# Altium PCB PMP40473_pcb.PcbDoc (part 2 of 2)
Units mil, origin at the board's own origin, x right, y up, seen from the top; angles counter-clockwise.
Board outline 3937.01 x 2598.43 mil, 2 copper layers (Top Layer, Bottom Layer), stack 62 mil thick; 79 components, 45 nets, 178 pads, 0 vias.
Unrouted connection lines stored in the file: 2.
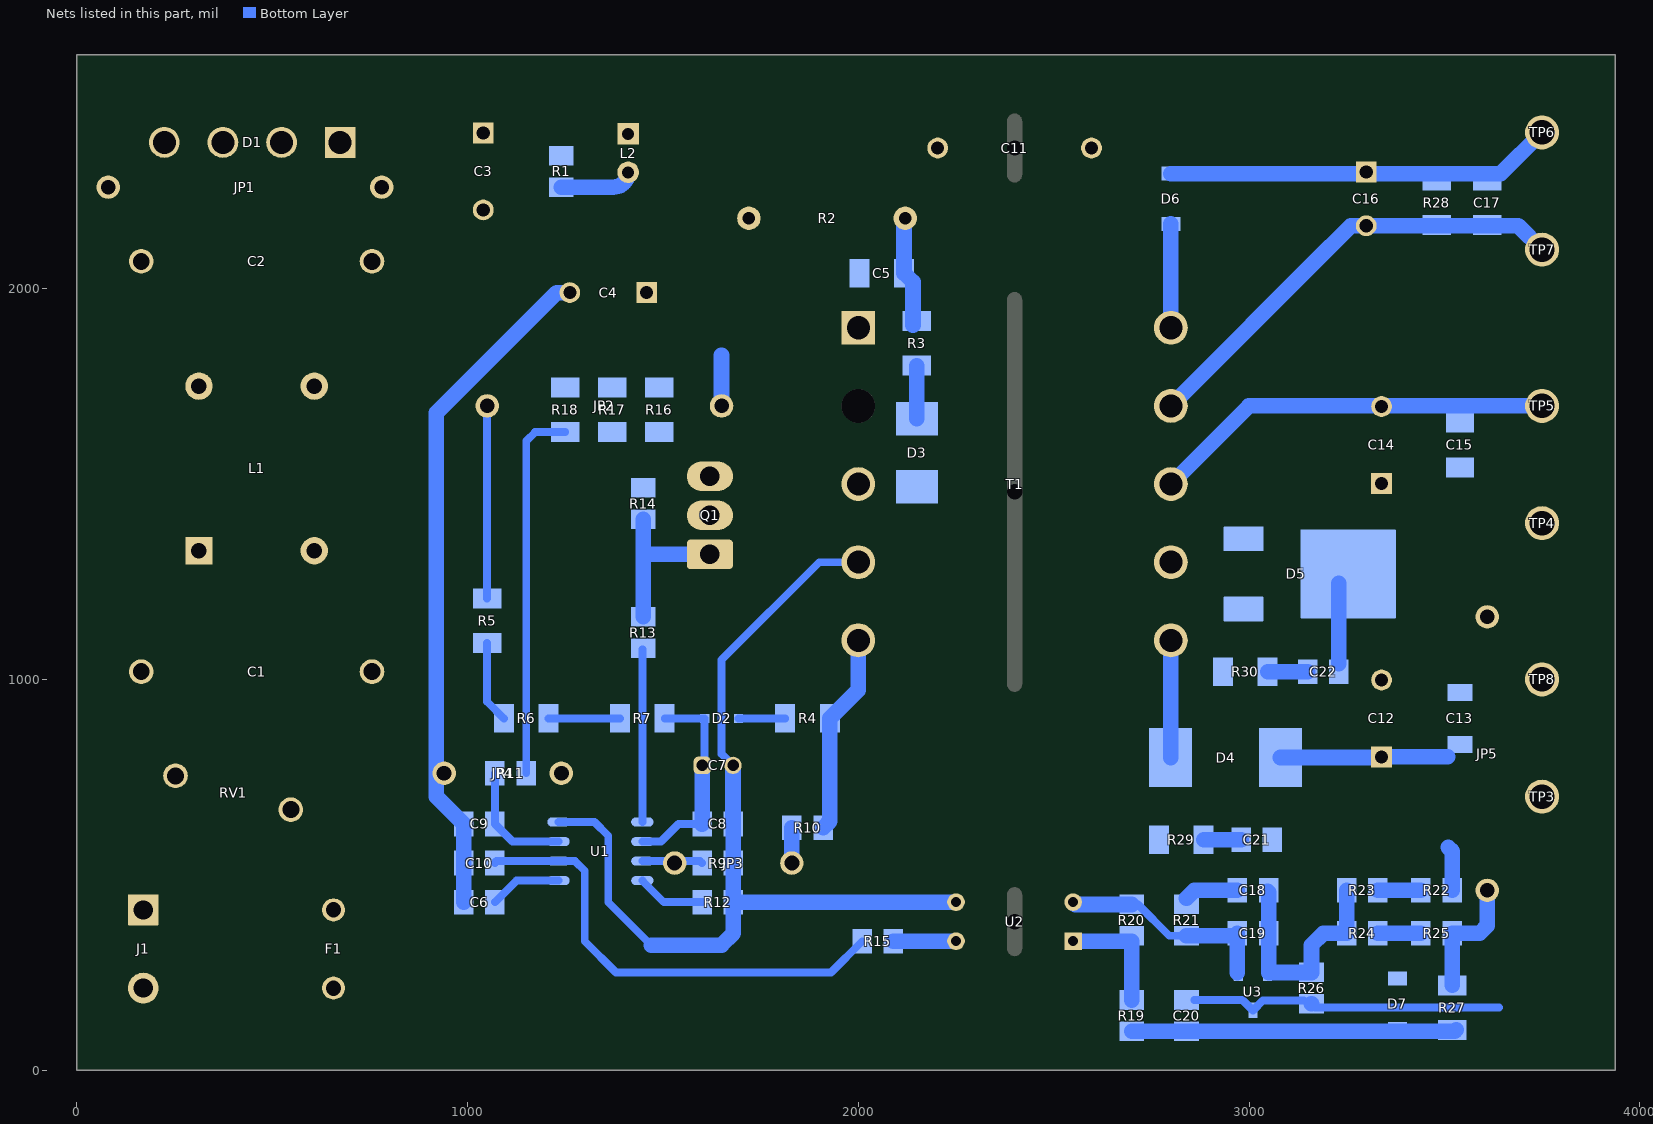
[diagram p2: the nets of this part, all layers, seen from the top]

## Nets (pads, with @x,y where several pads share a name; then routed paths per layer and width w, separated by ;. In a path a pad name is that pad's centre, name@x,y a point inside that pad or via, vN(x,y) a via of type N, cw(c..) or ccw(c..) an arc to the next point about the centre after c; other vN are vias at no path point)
12V: C14.1 C15.1 C22.2 D5.4 JP5.2 TP4.1 | length 206.1
  Bottom Layer w40: C22.2@3230,1040 D5.4@3230,1246.14
15V: C16.1 C17.1 D6.1 R28.2 TP6.1 | length 993.7
  Bottom Layer w40: D6.1@2800,2294.47 3644.47,2294.47 TP6.1@3750,2400
24V: C12.1 C13.1 C21.2 D4.1 R22.2 TP3.1 | length 542.8
  Bottom Layer w40: D4.1@3080.49,800 3337.8,800 C12.1@3339.37,801.57 3508.5,801.57 ; 3510,570 3520,560 R22.2@3520,460
NetC1_1: C1.1 F1.2 L1.2 RV1.2
NetC1_2: C1.2 J1.1 L1.1 RV1.1
NetC2_1: C2.1 D1.2 L1.3
NetC2_2: C2.2 D1.3 L1.4
NetC3_1: C3.1 D1.1 L2.1 R1.1
NetC4_1: C4.1 C5.1 JP2.2 L2.2 R1.2 R2.2 T1.1 | length 322.6
  Bottom Layer w40: R1.2@1240,2260 1373.07,2260 ccw(c1373.07,2297.87) L2.2@1410.95,2297.87 ; JP2.2@1650,1700 1650,1830
NetC5_2: C5.2 R2.1 R3.2 | length 283.6
  Bottom Layer w40: R2.1@2120,2180 2117.09,2177.09 C5.2@2117.09,2040 2140,2017.09 R3.2@2140,1907.09
NetC6_2: C6.2 U1.1 | length 185.5
  Bottom Layer w20: C6.2@1070,430 1125,485 U1.1@1232.72,485
NetC7_1: C7.1 C8.1 D2.1 R7.1 U1.6 | length 546.5
  Bottom Layer w20: U1.6@1447.28,585 1495,585 1540,630 C8.1@1600,630 ; R7.1@1504.37,900 D2.1@1606.69,900 1606.69,786.06 C7.1@1600.63,780
  Bottom Layer w40: C8.1@1600,630 1600.63,630.63 C7.1@1600.63,780
NetC9_1: C9.1 R11.1 U1.3 | length 311.4
  Bottom Layer w20: R11.1@1070,760 C9.1@1070,630 1115,585 U1.3@1232.72,585
NetC10_1: C10.1 R15.2 U1.2 | length 1199.5
  Bottom Layer w20: C10.1@1070,530 cw(c1075,530) 1075,535 U1.2@1232.72,535 1275,535 1300,510 1300,330 1380,250 1930,250 R15.2@2010,330
NetC16_2: C16.2 C17.2 R28.1 T1.9 TP7.1 | length 1745.7
  Bottom Layer w40: 3208.9,2110 2800,1701.1 T1.9@2800,1700 3261.1,2161.1 C16.2@3300,2161.1 3688.9,2161.1 TP7.1@3750,2100
NetC18_1: C18.1 C19.1 R23.1 R24.1 R26.2 U3.2 | length 897.8
  Bottom Layer w20: C18.1@3047.4,457.4 U3.2@3047.4,247.24 R26.2@3134.25,247.24
  Bottom Layer w40: C18.1@3047.4,457.4 3050.16,454.65 3050.16,250 R26.2@3160,250 3160,320 3190,350 R24.1@3250,350 R23.1@3250,460
NetC18_2: C18.2 R21.1 | length 138.3
  Bottom Layer w40: R21.1@2840,440 2860,460 C18.2@2970,460
NetC19_2: C19.2 R20.2 R21.2 U2.2 U3.1 | length 560.9
  Bottom Layer w20: R20.2@2700,424 2716,424 2796,344 R21.2@2840,344 ; U3.1@2972.6,247.24 U3.1@2972.6,249.84
  Bottom Layer w40: U2.2@2550,430 2556,424 R20.2@2700,424 ; R21.2@2840,344 2964,344 C19.2@2970,350 U3.1@2970,249.84
NetC20_1: C20.1 D7.1 R19.1 R27.2 | length 831.4
  Bottom Layer w40: R19.1@2700,99.5 C20.1@2840,99.5 3526.59,99.5 R27.2@3530,102.91
NetC21_1: C21.1 R29.1 | length 96.3
  Bottom Layer w40: R29.1@2883.73,590 C21.1@2980,590
NetC22_1: C22.1 R30.1 | length 102.4
  Bottom Layer w40: R30.1@3047.64,1020 C22.1@3150,1020
NetD2_2: D2.2 R4.1 | length 119.6
  Bottom Layer w20: D2.2@1693.31,900 R4.1@1812.91,900
NetD3_1: D3.1 R3.1 | length 135.9
  Bottom Layer w40: D3.1@2150,1667.01 R3.1@2150,1802.91
NetD3_2: D3.2 Q1.2 T1.3
NetD4_2: D4.2 R29.2 T1.6 | length 300.2
  Bottom Layer w40: D4.2@2799.51,800 2800,800.49 T1.6@2800,1100
NetD5_1: D5.1 D5.3 R30.2 T1.7
NetD6_2: D6.2 T1.10 | length 265.5
  Bottom Layer w40: T1.10@2800,1900 D6.2@2800,2165.53
NetF1_1: F1.1 J1.2
NetJP2_1: JP2.1 R5.2 | length 492.9
  Bottom Layer w20: R5.2@1050,1207.09 JP2.1@1050,1700
NetJP3_1: JP3.1 R9.2 U1.7 | length 154.8
  Bottom Layer w20: U1.7@1447.28,535 1595,535 R9.2@1600,530
NetJP3_2: JP3.2 R10.1 | length 90
  Bottom Layer w40: JP3.2@1830,530 R10.1@1830,620
NetJP5_1: JP5.1 R25.2 R27.1 | length 321.2
  Bottom Layer w40: R27.1@3520,217.09 R25.2@3520,350 3590,350 3610,370 JP5.1@3610,460
NetQ1_1: Q1.1 R13.1 R14.2 | length 420
  Bottom Layer w40: R13.1@1450,1160 1450,1320 ; R14.2@1450,1410 1450,1320 ; Q1.1@1620,1320 1450,1320
NetQ1_3: Q1.3 R11.2 R14.1 R16.2 R17.2 R18.2 | length 959.5
  Bottom Layer w20: R11.2@1150,760 1150,1610 1172.91,1632.91 R18.2@1250,1632.91
NetR4_2: R4.2 R10.2 T1.5 | length 517.3
  Bottom Layer w40: R10.2@1910,620 1927.09,637.09 R4.2@1927.09,900 2000,972.91 T1.5@2000,1100
NetR5_1: R5.1 R6.2 | length 210.7
  Bottom Layer w20: R5.1@1050,1092.91 1050,942.91 R6.2@1092.91,900
NetR6_1: R6.1 R7.2 | length 183.1
  Bottom Layer w20: R6.1@1207.09,900 R7.2@1390.2,900
NetR12_2: R12.2 U1.8 | length 175.5
  Bottom Layer w20: U1.8@1447.28,485 1502.28,430 R12.2@1600,430
NetR13_2: R13.2 U1.5 | length 442.3
  Bottom Layer w20: U1.5@1447.28,635 R13.2@1447.28,1077.28
NetR15_1: R15.1 U2.4 | length 160
  Bottom Layer w40: R15.1@2090,330 U2.4@2250,330
NetR19_2: R19.2 R20.1 U2.1 | length 300.5
  Bottom Layer w40: U2.1@2550,330 2700,330 R19.2@2700,179.5
NetR22_1: R22.1 R23.2 | length 110
  Bottom Layer w40: R23.2@3330,460 R22.1@3440,460
NetR24_2: R24.2 R25.1 | length 110
  Bottom Layer w40: R24.2@3330,350 R25.1@3440,350
PGND: C3.2 C4.2 C6.1 C7.2 C8.2 C9.2 C10.2 C11.1 D1.4 JP1.1 JP1.2 JP4.1 JP4.2 R9.1 R12.1 R16.1 R17.1 R18.1 T1.4 U1.4 U2.3 | length 4175.9
  Bottom Layer w20: U1.4@1232.72,635 1325,635 1360,600 1360,430 1470,320 ; C7.2@1679.37,780 1650,809.37 1650,1050 1900,1300 T1.4@2000,1300
  Bottom Layer w40: C6.1@990,430 C10.2@990,530 C9.2@990,630 920,700 920,1682 1228,1990 C4.2@1261.57,1990 ; 1470,320 1650,320 1680,350 R12.1@1680,430 ; C7.2@1679.37,780 1679.37,630.63 C8.2@1680,630 R12.1@1680,430 ; U2.3@2250,430 R12.1@1680,430
SGND: C11.2 C12.2 C13.2 C14.2 C15.2 C20.2 D7.2 R26.1 T1.8 TP5.1 TP8.1 U3.3 | length 1818.7
  Bottom Layer w20: C20.2@2860,179.5 2983.26,179.5 U3.3@3010,152.76 3035.75,178.5 R26.1@3140,178.5 ; R26.1@3160,170 3170,160 3640,160
  Bottom Layer w40: T1.8@2800,1500 3000,1700 TP5.1@3750,1700
pads on no net: T1.2

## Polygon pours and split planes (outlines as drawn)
NetC20_1 on Bottom Layer "Aux" (solid, pour order 56): 3550,25.49 cw(c3534.51,25.49) 3534.51,10 2675.49,10 cw(c2675.49,25.49) 2660,25.49 2660,109.02 cw(c2670,109.02) 2670,119.02 3550,119.02
NetR4_2 on Bottom Layer "Aux" (solid, pour order 50): 2060,1170 cw(c2060,1160) 2070,1160 2070,570 1885,570 1885,1160 cw(c1895,1160) 1895,1170 1905,1170
NetC7_1 on Bottom Layer "VCC" (solid, pour order 54): 1518.56,586.5 1492.26,570.02 1492.22,570.01 1492.18,570 1410,570 1410,600 1440,610 1500,610 1500,920 1516.81,936.81 1613.19,936.81 1620,930 1620,600 1606.5,586.5
PGND on Bottom Layer "PGND" (solid, remove dead copper, pour order 52): 2230,1340 2220,1350 2180,1350 1560,1350 1560,835 1520,810 1030,810 1030,380 970,440 970,990 940,1020 900,1020 900,0 2200,0 2230,0
NetQ1_3 on Bottom Layer "Bottom Layer-No Net" (solid, remove dead copper, pour order 40): 1220,1480 cw(c1220,1500) 1200,1500 1200,1650 cw(c1220,1650) 1220,1670 1580,1670 1690,1560 1690,1491.15 1678.85,1480
NetC2_1 on Bottom Layer "Bottom Layer-No Net" (solid, remove dead copper, pour order 38): 470,2450 cw(c480,2450) 480,2460 560,2460 cw(c560,2450) 570,2450 570,2420 570,2290 640,2220 700,2160 790,2160 cw(c790,2150) 800,2150 800,1716.02 cw(c783.98,1716.02) 783.98,1700 780,1700 490,1700 cw(c490,1720) 470,1720 470,2040 cw(c490,2040) 490,2060 710,2060 ccw(c710,2070) 720,2070 ccw(c710,2070) 710,2080 488.24,2080 cw(c488.24,2098.05) 470.19,2098.05 cw(c480,2100) 470,2100 470,2410
NetC2_2 on Bottom Layer "Bottom Layer-No Net" (solid, remove dead copper, pour order 36): 320,2450 cw(c330,2450) 330,2460 410,2460 cw(c410,2450) 420,2450 420,2420 420,2090 cw(c410,2090) 410,2080 210,2080 ccw(c210,2070) 200,2070 ccw(c210,2070) 210,2060 360,2060 cw(c360,2050) 370,2050 370,1720 cw(c350,1720) 350,1700 40,1700 cw(c40,1714.51) 25.49,1714.51 25.49,2050 cw(c35.49,2050) 35.49,2060 120,2060 ccw(c120,2070) 130,2070 ccw(c120,2070) 120,2080 33.5,2080 cw(c33.5,2088.01) 25.49,2088.01 25.49,2175.49 cw(c38.98,2175.49) 38.98,2188.98 191.02,2188.98 320,2317.95
NetC1_1 on Bottom Layer "Bottom Layer-No Net" (solid, remove dead copper, pour order 34): 490,360 cw(c490,380) 470,380 470,400 470,1000 470,1010 710,1010 ccw(c710,1020) 720,1020 ccw(c710,1020) 710,1030 470,1030 470,1380 cw(c490,1380) 490,1400 780,1400 cw(c780,1380) 800,1380 800,410 800,380 cw(c780,380) 780,360 750,360 560,360
NetC1_2 on Bottom Layer "Bottom Layer-No Net" (solid, remove dead copper, pour order 32): 370,400 370,380 cw(c350,380) 350,360 330,360 40,360 cw(c40,374.51) 25.49,374.51 25.49,1000 cw(c35.49,1000) 35.49,1010 120,1010 ccw(c120,1020) 130,1020 ccw(c120,1020) 120,1030 40,1030 cw(c40,1044.51) 25.49,1044.51 25.49,1385.49 cw(c40,1385.49) 40,1400 50,1400 350,1400 cw(c350,1380) 370,1380 370,1039.62 370,1030 210,1030 ccw(c210,1020) 200,1020 ccw(c210,1020) 210,1010 370,1010 370,1000
NetF1_1 on Bottom Layer "Bottom Layer-No Net" (solid, remove dead copper, pour order 30): 25.49,44.51 25.49,245.49 cw(c40,245.49) 40,260 780,260 785.49,260 cw(c785.49,245.49) 800,245.49 800,44.51 cw(c785.49,44.51) 785.49,30 780,30 40,30 cw(c40,44.51)
NetD6_2 on Bottom Layer "Bottom Layer-No Net" (solid, remove dead copper, pour order 16): 2650,1830 ccw(c2664.51,1830) 2664.51,1815.49 2785.49,1815.49 2990,2020 2990,2200 ccw(c2980,2200) 2980,2210 2660,2210 ccw(c2660,2200) 2650,2200 2650,2190
SGND on Bottom Layer "Bottom Layer-No Net" (solid, remove dead copper, pour order 14): 2660,1604.51 ccw(c2660,1594.51) 2650,1594.51 2650,1590 2650,540 2650,80 2660,70 3920,70 3920,1970 3911.52,1970 3911.52,2596.91 3908.43,2600 2770,2600 2708.43,2598.43 2560,2450 2560,2300 2570,2290 2700,2290 2720,2270 2720,1604.51
NetD5_1 on Bottom Layer "Bottom Layer-No Net" (solid, pour order 12): 2903.11,930 cw(c2903.11,937.05) 2896.06,937.05 2896.06,1127.24 2853.3,1170 2670,1170 2660,1170 cw(c2660,1180) 2650,1180 2650,1390 cw(c2660,1390) 2660,1400 2670,1400 3070,1400 3070,1070 2997.05,1070 2997.05,937.05 cw(c2990,937.05) 2990,930
24V on Bottom Layer "Bottom Layer-No Net" (solid, pour order 10): 3050,540 cw(c3050,560) 3030,560 3030,640 ccw(c3020,640) 3020,650 2901.42,650 cw(c2901.42,651.42) 2900,651.42 2900,870 cw(c2910,870) 2910,880 3810,880 cw(c3805,855) 3830,850 3830,560 cw(c3810,560) 3810,540
NetD4_2 on Bottom Layer "Bottom Layer-No Net" (solid, pour order 8): 2840,1140 cw(c2840,1120) 2860,1120 2860,566.86 2833.14,540 2650,540 2650,1130 cw(c2660,1130) 2660,1140 2670,1140
12V on Bottom Layer "Bottom Layer-No Net" (solid, pour order 6): 3120,1140 ccw(c3140,1140) 3140,1120 3800,1120 ccw(c3800,1140) 3820,1140 3820,1560 ccw(c3795,1565) 3800,1590 3150,1590 ccw(c3150,1560) 3120,1560
NetC16_2 on Bottom Layer "Bottom Layer-No Net" (solid, pour order 2): 3810,2030 ccw(c3810,2050) 3830,2050 3830,2190 ccw(c3810,2190) 3810,2210 3220,2210 2800,1790 2660,1790 ccw(c2660,1780) 2650,1780 2650,1640 ccw(c2660,1640) 2660,1630 2800,1630 3200,2030
15V on Bottom Layer "Bottom Layer-No Net" (solid, pour order 0): 3810,2240 ccw(c3810,2260) 3830,2260 3830,2430 ccw(c3810,2430) 3810,2450 2720,2450 ccw(c2720,2430) 2700,2430 2700,2260 ccw(c2720,2260) 2720,2240
PGND on Bottom Layer "Bottom Layer-No Net" (solid, pour order 18): 25.49,2230 ccw(c35.49,2230) 35.49,2220 40,2220 180,2220 270,2310 270,2460 330,2520 2010,2520 2120,2410 2120,2300 2130,2290 2230,2290 2240,2300 2240,2450 2091.57,2598.43 2030,2598.43 30,2598.43 ccw(c30,2593.91) 25.49,2593.91
NetC4_1 on Bottom Layer "Bottom Layer-No Net" (solid, remove dead copper, pour order 20): 1520,2330 ccw(c1520,2320) 1510,2320 1510,2030 cw(c1500,2030) 1500,2020 cw(c1500,2030) 1490,2030 1490,2320 ccw(c1480,2320) 1480,2330 1475.49,2330 1370,2330 1320,2280 1320,2060 1590,1790 2040,1790 2040,2210 1920,2330
NetC5_2 on Bottom Layer "Bottom Layer-No Net" (solid, pour order 22): 2220,2230 2230,2220 2230,1870 2210,1850 2100,1850 2090,1850 2080,1860 2080,2220 2090,2230
PGND on Bottom Layer "BOTTOM_LAYER_PGND_P024" (solid, remove dead copper, pour order 24): 1139,1874 1130,1870 1110,1870 1099.15,1880.85 1099.15,1913.85 1064,1949 932,2081 932,2090.79 1018.71,2177.5 ccw(c1016.64,2179.57) 1014.58,2181.64 927.93,2095 918,2095 813,2200 710,2200 670,2240 670,2290 cw(c680,2290) 680,2300 1010,2300 1070,2240 1530,1780 1540,1770 1540,1730 cw(c1517.68,1730) 1517.68,1707.68 1162.32,1707.68 cw(c1162.32,1727) 1143,1727 1143,1860 1244,1961 1244,1966 1240,1970 1235,1970
NetC3_1 on Bottom Layer "Bottom Layer-No Net" (solid, remove dead copper, pour order 26): 1490,2370 cw(c1475.49,2370) 1475.49,2355.49 1355.49,2355.49 1330,2330 620,2330 620,2420 620,2440 cw(c650,2440) 650,2470 1470,2470 cw(c1470,2450) 1490,2450 1490,2440
NetD3_2 on Bottom Layer "Bottom Layer-No Net" (solid, remove dead copper, pour order 28): 1730,1570 1730,1519.42 1672.1,1461.51 1626.7,1456.7 1620,1450 1620,1390 1630,1380 1660,1380 2210,1380 ccw(c2210,1400) 2230,1400 2230,1580 ccw(c2205,1575) 2200,1600 1760,1600

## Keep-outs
Keep-Out Layer:
  text ".Layer_Name" at 577,-858.49 h60

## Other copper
Top Layer:
  text ".Layer_Name" at 577,-858.49 h60
Bottom Layer:
  text ".Layer_Name" at 577,-858.49 h60

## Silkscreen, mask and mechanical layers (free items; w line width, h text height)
Top Overlay:
  region: 3660,230 3360,230 3360,130 3660,130
  text "15V/20mA" at 3911.52,2046.02 h100 r90
  text "12V/0.9A" at 3910,1370 h100 r90
  text "24V/0.5A" at 3910,670 h100 r90
  text "'.PRJ_Number'.PCB_Rev-" at 2775,145.77 h108.27
  text "INPUT: 85-115VAC" at 440,40 h100
  text ".Layer_Name" at 577,-858.49 h60
Bottom Overlay:
  lines w5: 2242.52,0 2242.52,2598.43 ; 2555.48,0 2555.48,2598.43
  text ".Layer_Name" at 577,-858.49 h60
Top Paste:
  text ".Layer_Name" at 577,-858.49 h60
Bottom Paste:
  text ".Layer_Name" at 577,-858.49 h60
Top Solder:
  text ".Layer_Name" at 577,-858.49 h60
  text ".Layer_Name" at 577,-858.49 h60
Bottom Solder:
  text ".Layer_Name" at 577,-858.49 h60
Drill Guide:
  text ".Layer_Name" at 577,-858.49 h60
M1 Board Outline:
  the board outline again, w10
  text ".Layer_Name" at 577,-858.49 h60
M2 Board Dimensions:
  rectangle: 0,-275 125,-150
  rectangle: 125,-400 500,-275
  lines w7: 0,-275 1000,-275 ; 125,-400 125,-150 ; 250,-400 250,-150 ; 500,-400 500,-150 ; 750,-400 750,-150 ; 0,-400 1000,-400 1000,-150 0,-150 0,-400
  text ".Layer_Name" at 577,-858.49 h60
M3 3D STEP Top:
  text ".Layer_Name" at 577,-858.49 h60
M4 3D STEP Bottom:
  text ".Layer_Name" at 577,-858.49 h60
M5 Assembly Top:
  lines w10: -292,-930.17 6308,-930.17 ; -292,-726.83 6310,-726.83 ; -292,-523.5 -292,-1133.5 3713,-1133.5 6310,-1133.5 6310,-523.5 -291.5,-523.5 -291.5,-1133.5 1284,-1133.5 ; 2173,-1133.5 2173,-523.5 ; 3440,-726.83 3440,-523.5 ; 4280,-726.83 4280,-523.5 ; 4902,-1140 4902,-937.17
  text "COMPONENTS MARKED 'DNP' SHOULD NOT BE POPULATED." at 1153.5,-318.5 h60
  text "ASSEMBLY VARIANT:" at 1153,-434 h60
  text ".VariantName" at 2189,-434 h60
  text "PCB VIEWED FROM TOP SIDE" at -228.5,-655.67 h60
  text "BOARD #:" at 2248,-655.67 h60
  text ".PRJ_Number" at 2793.5,-655.67 h60
  text "REV:" at 3638,-655.67 h60
  text ".PCB_Rev" at 3929.5,-655.67 h60
  text "SVN REV:" at 4476,-655.67 h60
  text ".VersionControl_RevNumber" at 4982,-655.67 h60
  text "TID #:" at 2248,-859 h60
  text ".TID" at 2793.5,-859 h60
  text "PLOT NAME =" at -228.5,-1064.34 h60
  text ".plot_File_Name" at 577,-1064.34 h60
  text "GENERATED    :" at 2250,-1064.34 h60
  text ".Print_Date" at 3119.5,-1064.34 h60
  text ".Print_Time" at 3848.5,-1064.34 h60
  text "TEXAS INSTRUMENTS" at 5113,-1064.34 h60
M6 Assembly Bottom:
  lines w10: -292.5,-727.33 6309.5,-727.33 ; -290.5,-930.67 6309.5,-930.67 ; 1115.5,-1140.5 1115.5,-937.67 ; 1737.5,-727.33 1737.5,-524 ; 2577.5,-727.33 2577.5,-524 ; 3844.5,-1134 3844.5,-524 ; 4733.5,-1134 6309,-1134 6309,-524 -292.5,-524 -292.5,-1134 2304.5,-1134 6309.5,-1134 6309.5,-524
  text "COMPONENTS MARKED 'DNP' SHOULD NOT BE POPULATED." at 6102,-318 h60
  text ".VariantName" at 5058,-434 h60
  text "ASSEMBLY VARIANT:" at 6097,-434 h60
  text ".VersionControl_RevNumber" at 1035.5,-656.17 h60
  text "SVN REV:" at 1541.5,-656.17 h60
  text ".PCB_Rev" at 2088,-656.17 h60
  text "REV:" at 2379.5,-656.17 h60
  text ".PRJ_Number" at 3224,-656.17 h60
  text "BOARD #:" at 3769.5,-656.17 h60
  text "PCB VIEWED FROM BOTTOM SIDE" at 6246,-656.17 h60
  text ".TID" at 3224,-859.5 h60
  text "TID #:" at 3769.5,-859.5 h60
  text "TEXAS INSTRUMENTS" at 904.5,-1064.84 h60
  text ".Print_Time" at 2169,-1064.84 h60
  text ".Print_Date" at 2898,-1064.84 h60
  text "GENERATED    :" at 3767.5,-1064.84 h60
  text ".plot_File_Name" at 5440.5,-1064.84 h60
  text "PLOT NAME =" at 6246,-1064.84 h60
M9 Title Sheet:
  drawing of 57 lines, arcs and shapes, not listed
  text "1" at 739.84,8036.5 h70
  text "2" at 3235.5,8036.5 h70
  text "3" at 5724.84,8036.5 h70
  text "4" at 8231.51,8036.5 h70
  text "5" at 10730.5,8036.5 h70
  text "6" at 13235.5,8036.5 h70
  text "A" at -416.5,6893.5 h70
  text "A" at 14383.5,6893.5 h70
  text "B" at -416.5,4513.5 h70
  text "B" at 14383.5,4513.5 h70
  text "C" at -416.5,2138.5 h70
  text "C" at 14383.5,2138.5 h70
  text "PROJECT TITLE:" at 11343.5,277.5 h45
  text ".PRJ_Title" at 11393.5,144.17 h70
  text "DESIGNED FOR:" at 11343.5,-23.5 h45
  text ".PRJ_Customer" at 11393.5,-163.5 h70
  text "D" at -416.5,-231.5 h70
  text "D" at 14383.5,-231.5 h70
  text "FILE NAME:" at 11343.5,-323.5 h45
  text ".PCB_File_Name_No_Path" at 11393.5,-443.5 h70
  text "Texas Instruments (TI) and/or its licensors do not warrant the accuracy or completeness of this specification" at 6374,-605.34 h45
  text "ENGINEER:" at 11343.5,-613.5 h45
  text "LAYOUT BY:" at 12848.5,-613.5 h45
  text "or any information contained therein. TI and/or its licensors do not warrant that this design will meet" at 6329.01,-718 h45
  text ".PRJ_Engineer" at 11393.5,-768.49 h70
  text ".PCB_Layout" at 12899,-768.49 h70
  text "the specifications, will be suitable for your application or fit for any particular purpose, or will operate in" at 6329.01,-830.67 h45
  text ".Layer_Name" at 577,-858.49 h60
  text "ALTIUM DESIGNER VERSION:" at 12848.5,-923.5 h45
  text "an implementation. TI and/or its licensors do not warrant that the design is production worthy. You should" at 6329.01,-943.33 h45
  text "completely validate and test your design implementation to confirm the system functionality for your application." at 6374,-1056 h45
  text ".print_Scale" at 11393.5,-1056.83 h70
  text ".Application_BuildNumber" at 12899,-1056.83 h70
  text "1" at 739.84,-1263.5 h70
  text "2" at 3235.5,-1263.5 h70
  text "3" at 5724.84,-1263.5 h70
  text "4" at 8231.51,-1263.5 h70
  text "5" at 10730.5,-1263.5 h70
  text "6" at 13235.5,-1263.5 h70
M10 Fab Notes:
  drawing of 189 lines, arcs and shapes, not listed
  text "DESIGN INFORMATION" at 12382.02,6356.17 h60
  text "MIN. TRACK WIDTH:" at 11737.46,6224.05 h60
  text "8" at 12833.7,6224.05 h60
  text "MIL" at 12988.46,6224.05 h60
  text "MIN. CLEARANCE:" at 11737.46,6099.92 h60
  text "0.2" at 12773.7,6099.93 h60
  text "mm" at 12988.46,6099.92 h60
  text "MIN. VIA PAD SIZE:" at 11737.46,5975.8 h60
  text "24" at 12803.71,5975.8 h60
  text "MIL" at 12988.46,5975.8 h60
  text "0.05mm (2MIL)" at 12432.46,5845.9 h60
  text "MINIMUM ANNULAR RING" at 11408.23,5837.67 h60
  text "EXTERNAL" at 13140.46,5837.67 h60
  text "PER" at 11608.23,5727.55 h60
  text "IPC-D-275 CLASS 2 LEVEL C" at 11828.23,5727.54 h60
  text "MIL, HOLES" at 13316.46,5627.07 h60
  text "+/-" at 12924,5618.48 h60
  text "+/-" at 13778,5618.48 h60
  text "REGISTRATION TOLERANCES:" at 11408.23,5617.42 h60
  text "METAL" at 12608,5617.42 h60
  text "5" at 13184.2,5617.42 h60
  text "3" at 14017.2,5617.42 h60
  text "MIL" at 14133.46,5617.42 h60
  text "HOLE SIZE TOLERANCE (UNLESS OTHERWISE SPECIFIED):" at 11408.23,5519.1 h60
  text "+/-" at 13778,5516.23 h60
  text "3" at 14017.2,5515.17 h60
  text "MIL" at 14133.46,5515.17 h60
  text "MATERIAL:" at 11333.46,5377.52 h60
  text "FR-4 High Tg" at 12319.9,5249 h60
  text "X" at 12175.46,5241.01 h60
  text "FR-408" at 11754.46,5236.49 h60
  text "OTHER" at 13242.46,5236.49 h60
  text "62 MIL (1.6mm) +/-10%" at 12074.56,5093.46 h60
  text "X" at 11954.46,5091.01 h60
  text "THICKNESS:" at 11408.23,5085.24 h60
  text "OTHER" at 13359.46,5085.24 h60
  text "TOLERANCE:" at 11408.23,4946.92 h60
  text "X" at 12256.46,4946.92 h60
  text "ANSI IPC-6012 TYPE 3 CLASS 2" at 12434.48,4946.92 h60
  text "OTHER +/-" at 12434.46,4802.73 h60
  text "BOW & TWIST:" at 11408.23,4657.54 h60
  text "X" at 12256.46,4657.54 h60
  text "ANSI IPC-6012 TYPE 3 CLASS 2" at 12434.48,4657.54 h60
  text "OTHER +/-" at 12434.46,4510.85 h60
  text "DRILLING:" at 11333.46,4380.23 h60
  text "NC_DRILL FILES" at 13094.46,4275.04 h60
  text "REFERENCE:" at 11408.23,4271.1 h60
  text "X" at 12065.46,4271.01 h60
  text "AS SHOWN" at 12243.46,4271.1 h60
  text "X" at 12966.46,4271.1 h60
  text "OTHER" at 13392.46,4128.85 h60
  text "PTH COPPER THICKNESS:" at 11407.91,4125.32 h60
  text "X" at 12547.14,4125.32 h60
  text "20-30 um" at 12675.14,4125.32 h60
  text "BOARD FINISH:" at 11333.46,3977.73 h60
  text "SILKSCREEN:" at 11488.68,3867.6 h60
  text "X" at 12446.46,3867.6 h60
  text "TOP" at 12563.46,3867.6 h60
  text "X" at 12956.46,3867.6 h60
  text "BOTTOM" at 13074.46,3867.6 h60
  text "SILKSCREEN COLOR:" at 11488.68,3712.41 h60
  text "X" at 12445.46,3712.41 h60
  text "WHITE" at 12563.46,3712.41 h60
  text "OTHER" at 13074.46,3712.41 h60
  text "X" at 12576.46,3568.96 h60
  text "GREEN" at 12694.46,3568.96 h60
  text "OTHER" at 13312.46,3568.96 h60
  text "SOLDER RESIST COLOR:" at 11488.68,3562.1 h60
  text "X" at 12576.46,3414.71 h60
  text "MATTE" at 12694.46,3414.71 h60
  text "SEMI-GLOSS" at 13312,3414.07 h60
  text "IMMERSION GOLD (ENIG)" at 12394.46,3241.94 h60
  text "ENEPIG" at 13732,3234.72 h60
  text "SURFACE FINISH:" at 11333.46,3233.72 h60
  text "X" at 12216.46,3233.72 h60
  text "IMM. TIN/SILVER OR EQUIV" at 11663,3096.4 h60
  text "OTHER" at 13094.46,3092.47 h60
  text "ARRAY/PANEL:" at 11333.46,2937.09 h60
  text "CUT AND TRIM PER M1 BOARD OUTLINE" at 12394.46,2928.87 h60
  text "N.C. ROUTE" at 12394.46,2792.9 h60
  text "X" at 13082.46,2792.9 h60
  text "V. SCORE" at 13260.46,2792.9 h60
  text "CERTIFICATION:" at 11333.46,2663.77 h60
  text "MATERIALS AND WORKMANSHIP FOR ALL PCBS" at 12058.46,2663.77 h60
  text "TO MEET OR EXCEED THE REQUIREMENTS OF:" at 12058.46,2569.71 h60
  text "X" at 11695.97,2441.08 h60
  text "ANSI IPC-A-600F CLASS ->" at 11823.96,2441.08 h60
  text "X" at 13471.97,2441.08 h60
  text "2" at 13581.96,2441.08 h60
  text "1" at 13266.96,2439.58 h60
  text "3" at 13935.96,2439.58 h60
  text "X" at 12507.97,2293.39 h60
  text "RoHS" at 12635.96,2293.39 h60
  text "OTHER" at 13280.36,2293.39 h60
  text "PER ORDER" at 13677.42,2293.39 h60
  text "ALL BOARDS MUST MEET OR EXCEED UL94-V0 REQUIREMENTS." at 11361,2139.57 h60
  text "PCB MUST BEAR THE UL94V-0 UL REGISTERED MATERIAL ID NUMBER" at 11361,2023.5 h60
  text "ADDITIONAL REQUIREMENTS:" at 11333.46,1854.08 h60
  text "MICROSECTION:" at 11408.23,1746.95 h60
  text "YES" at 12313.96,1746.95 h60
  text "REQUIRED" at 13175.46,1602.62 h60
  text "BARE BOARD ELEC. TEST:" at 11408.23,1599.76 h60
  text "NONE" at 12713.96,1599.76 h60
  text "X" at 13057.46,1599.76 h60
  text "PER ORDER" at 13767.46,1599.76 h60
  text "XX MIL VIAS REQUIRE NON-CONDUCTIVE FILL AND PLANARIZE" at 11576.38,1394.82 h59
  text "XX MIL VIAS REQUIRE CONDUCTIVE FILL AND PLANARIZE" at 11584.38,1290.84 h60
  text "OUTER XX MIL TRACES REQUIRE 50 OHM SINGLE-ENDED IMPEDANCE" at 11583.39,1127.46 h58
  text "LAYER 2 & 3 (INNER LAYERS) XX MIL WIDE, XX MIL SPACE / TRACES REQUIRE 100 OHM DIFFERENTIAL IMPEDANCE" at 11575.39,891.74 h60
  text ".Layer_Name" at 577,-858.49 h60
M11 Gerber Information:
  lines w10: -292,-930.17 6308,-930.17 ; -292,-726.83 6310,-726.83 ; -292,-523.5 -292,-1133.5 3713,-1133.5 6310,-1133.5 6310,-523.5 -291.5,-523.5 -291.5,-1133.5 1284,-1133.5 ; 2173,-1133.5 2173,-523.5 ; 3440,-726.83 3440,-523.5 ; 4280,-726.83 4280,-523.5 ; 4902,-1140 4902,-937.17
  text "ALL ARTWORK VIEWED FROM TOP SIDE" at -228.5,-655.67 h60
  text "BOARD #:" at 2248,-655.67 h60
  text ".PRJ_Number" at 2793.5,-655.67 h60
  text "REV:" at 3638,-655.67 h60
  text ".PCB_Rev" at 3929.5,-655.67 h60
  text "SVN REV:" at 4476,-655.67 h60
  text ".VersionControl_RevNumber" at 4982,-655.67 h60
  text "LAYER NAME =" at -228.5,-858.49 h60
  text "TID #:" at 2248,-859 h60
  text ".TID" at 2793.5,-859 h60
  text "PLOT NAME =" at -228.5,-1064.34 h60
  text ".plot_File_Name" at 577,-1064.34 h60
  text "GENERATED    :" at 2250,-1064.34 h60
  text ".Print_Date" at 3119.5,-1064.34 h60
  text ".Print_Time" at 3848.5,-1064.34 h60
  text "TEXAS INSTRUMENTS" at 5113,-1064.34 h60
M12 Stackup:
  drawing of 191 lines, arcs and shapes, not listed
  text "Layer" at 9797.84,7830 h60
  text "Name" at 10207.76,7830 h60
  text "Material" at 11137.5,7830 h60
  text "Thickness" at 11997.27,7830 h60
  text "Constant" at 12647.1,7830 h60
  text "Board Layer Stack" at 13216.96,7830 h60
  text "1" at 9797.84,7710 h60
  text "Top Overlay" at 10207.76,7710 h60
  text "2" at 9797.84,7590 h60
  text "Top Solder" at 10207.76,7590 h60
  text "Solder Resist" at 11137.5,7590 h60
  text "0.40mil" at 11997.27,7590 h60
  text "3.5" at 12647.1,7590 h60
  text "3" at 9797.84,7470 h60
  text "Top Layer" at 10207.76,7470 h60
  text "Copper" at 11137.5,7470 h60
  text "1.40mil" at 11997.27,7470 h60
  text "4" at 9797.84,7350 h60
  text "Dielectric1" at 10207.76,7350 h60
  text "FR-4" at 11137.5,7350 h60
  text "59.20mil" at 11997.27,7350 h60
  text "4.8" at 12647.1,7350 h60
  text "5" at 9797.84,7230 h60
  text "Bottom Layer" at 10207.76,7230 h60
  text "Copper" at 11137.5,7230 h60
  text "1.40mil" at 11997.27,7230 h60
  text "6" at 9797.84,7110 h60
  text "Bottom Solder" at 10207.76,7110 h60
  text "Solder Resist" at 11137.5,7110 h60
  text "0.40mil" at 11997.27,7110 h60
  text "3.5" at 12647.1,7110 h60
  text "7" at 9797.84,6990 h60
  text "Bottom Overlay" at 10207.76,6990 h60
  text ".Layer_Name" at 577,-858.49 h60
M13 Component Bodies Top:
  text ".Layer_Name" at 577,-858.49 h60
M14 Component Bodies Bottom:
  text ".Layer_Name" at 577,-858.49 h60
M15 Courtyards Top:
  text ".Layer_Name" at 577,-858.49 h60
M16 Courtyards Bottom:
  text ".Layer_Name" at 577,-858.49 h60
Drill Drawing:
  drawing of 160 lines, arcs and shapes, not listed
  text "Symbol" at 5345.77,3385.59 h72
  text "Quantity" at 5631.52,3385.59 h72
  text "Finished Hole Size" at 5948.7,3385.59 h72
  text "Plated" at 6570.45,3385.59 h72
  text "Hole Type" at 6814.77,3385.59 h72
  text "Drill Layer Pair" at 7175.11,3385.59 h72
  text "Hole Tolerance" at 7884.62,3385.59 h72
  text "4" at 5631.52,3285.96 h60
  text "25.59mil (0.650mm)" at 5948.7,3285.96 h60
  text "PTH" at 6570.45,3285.96 h60
  text "Round" at 6814.77,3285.96 h60
  text "Top Layer - Bottom Layer" at 7175.11,3285.96 h60
  text "2" at 5631.52,3186.34 h60
  text "29.53mil (0.750mm)" at 5948.7,3186.34 h60
  text "PTH" at 6570.45,3186.34 h60
  text "Round" at 6814.77,3186.34 h60
  text "Top Layer - Bottom Layer" at 7175.11,3186.34 h60
  text "2" at 5631.52,3086.72 h60
  text "31.00mil (0.787mm)" at 5948.7,3086.72 h60
  text "PTH" at 6570.45,3086.72 h60
  text "Round" at 6814.77,3086.72 h60
  text "Top Layer - Bottom Layer" at 7175.11,3086.72 h60
  text "2" at 5631.52,2987.1 h60
  text "32.00mil (0.813mm)" at 5948.7,2987.1 h60
  text "PTH" at 6570.45,2987.1 h60
  text "Round" at 6814.77,2987.1 h60
  text "Top Layer - Bottom Layer" at 7175.11,2987.1 h60
  text "12" at 5631.52,2887.47 h60
  text "33.47mil (0.850mm)" at 5948.7,2887.47 h60
  text "PTH" at 6570.45,2887.47 h60
  text "Round" at 6814.77,2887.47 h60
  text "Top Layer - Bottom Layer" at 7175.11,2887.47 h60
  text "6" at 5631.52,2787.85 h60
  text "37.00mil (0.940mm)" at 5948.7,2787.85 h60
  text "PTH" at 6570.45,2787.85 h60
  text "Round" at 6814.77,2787.85 h60
  text "Top Layer - Bottom Layer" at 7175.11,2787.85 h60
  text "B" at 5324.14,2777.86 h44.28
  text "4" at 5631.52,2688.23 h60
  text "38.00mil (0.965mm)" at 5948.7,2688.23 h60
  text "PTH" at 6570.45,2688.23 h60
  text "Round" at 6814.77,2688.23 h60
  text "Top Layer - Bottom Layer" at 7175.11,2688.23 h60
  text "A" at 5324.14,2678.24 h44.28
  text "2" at 5631.52,2588.61 h60
  text "39.37mil (1.000mm)" at 5948.7,2588.61 h60
  text "PTH" at 6570.45,2588.61 h60
  text "Round" at 6814.77,2588.61 h60
  text "Top Layer - Bottom Layer" at 7175.11,2588.61 h60
  text "4" at 5631.52,2488.98 h60
  text "40.00mil (1.016mm)" at 5948.7,2488.98 h60
  text "PTH" at 6570.45,2488.98 h60
  text "Round" at 6814.77,2488.98 h60
  text "Top Layer - Bottom Layer" at 7175.11,2488.98 h60
  text "6" at 5631.52,2389.36 h60
  text "43.31mil (1.100mm)" at 5948.7,2389.36 h60
  text "PTH" at 6570.45,2389.36 h60
  text "Round" at 6814.77,2389.36 h60
  text "Top Layer - Bottom Layer" at 7175.11,2389.36 h60
  text "2" at 5631.52,2289.74 h60
  text "49.21mil (1.250mm)" at 5948.7,2289.74 h60
  text "PTH" at 6570.45,2289.74 h60
  text "Round" at 6814.77,2289.74 h60
  text "Top Layer - Bottom Layer" at 7175.11,2289.74 h60
  text "3" at 5631.52,2190.12 h60
  text "50.00mil (1.270mm)" at 5948.7,2190.12 h60
  text "PTH" at 6570.45,2190.12 h60
  text "Round" at 6814.77,2190.12 h60
  text "Top Layer - Bottom Layer" at 7175.11,2190.12 h60
  text "13" at 5631.52,2090.5 h60
  text "59.06mil (1.500mm)" at 5948.7,2090.5 h60
  text "PTH" at 6570.45,2090.5 h60
  text "Round" at 6814.77,2090.5 h60
  text "Top Layer - Bottom Layer" at 7175.11,2090.5 h60
  text "C" at 5324.14,2080.5 h44.28
  text "6" at 5631.52,1990.87 h60
  text "63.00mil (1.600mm)" at 5948.7,1990.87 h60
  text "PTH" at 6570.45,1990.87 h60
  text "Round" at 6814.77,1990.87 h60
  text "Top Layer - Bottom Layer" at 7175.11,1990.87 h60
  text "1" at 5631.52,1891.25 h60
  text "86.61mil (2.200mm)" at 5948.7,1891.25 h60
  text "PTH" at 6570.45,1891.25 h60
  text "Round" at 6814.77,1891.25 h60
  text "Top Layer - Bottom Layer" at 7175.11,1891.25 h60
  text "2" at 5631.52,1791.63 h60
  text "39.37mil (1.000mm)" at 5948.7,1791.63 h60
  text "PTH" at 6570.45,1791.63 h60
  text "Slot" at 6814.77,1791.63 h60
  text "Top Layer - Bottom Layer" at 7175.11,1791.63 h60
  text "1" at 5631.52,1692.01 h60
  text "39.37mil (1.000mm)" at 5948.7,1692.01 h60
  text "PTH" at 6570.45,1692.01 h60
  text "Slot" at 6814.77,1692.01 h60
  text "Top Layer - Bottom Layer" at 7175.11,1692.01 h60
  text "72 Total" at 5631.52,1592.38 h60
  text "Slot definitions :" at 5345.77,1512.77 h60
  text "Routed Path Length" at 5789.08,1512.77 h60
  text "= Calculated from tool start centre position to tool end centre position." at 6321.41,1512.77 h60
  text "Hole Length" at 5789.08,1463.04 h60
  text "= Routed Path Length + Tool Size = Slot length as defined in the PCB layout" at 6121.61,1463.04 h60
  text ".Layer_Name" at 577,-858.49 h60
M17 Embedded Cavity:
  text ".Layer_Name" at 577,-858.49 h60
M18 Embedded Assembly:
  text ".Layer_Name" at 577,-858.49 h60
M19 Embedded Keepout:
  text ".Layer_Name" at 577,-858.49 h60

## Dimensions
0,-400 to 1000,-400 on M2 Board Dimensions
0,0 to 3937.01,0 on M2 Board Dimensions
0,0 to 0,2598.43 on M2 Board Dimensions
